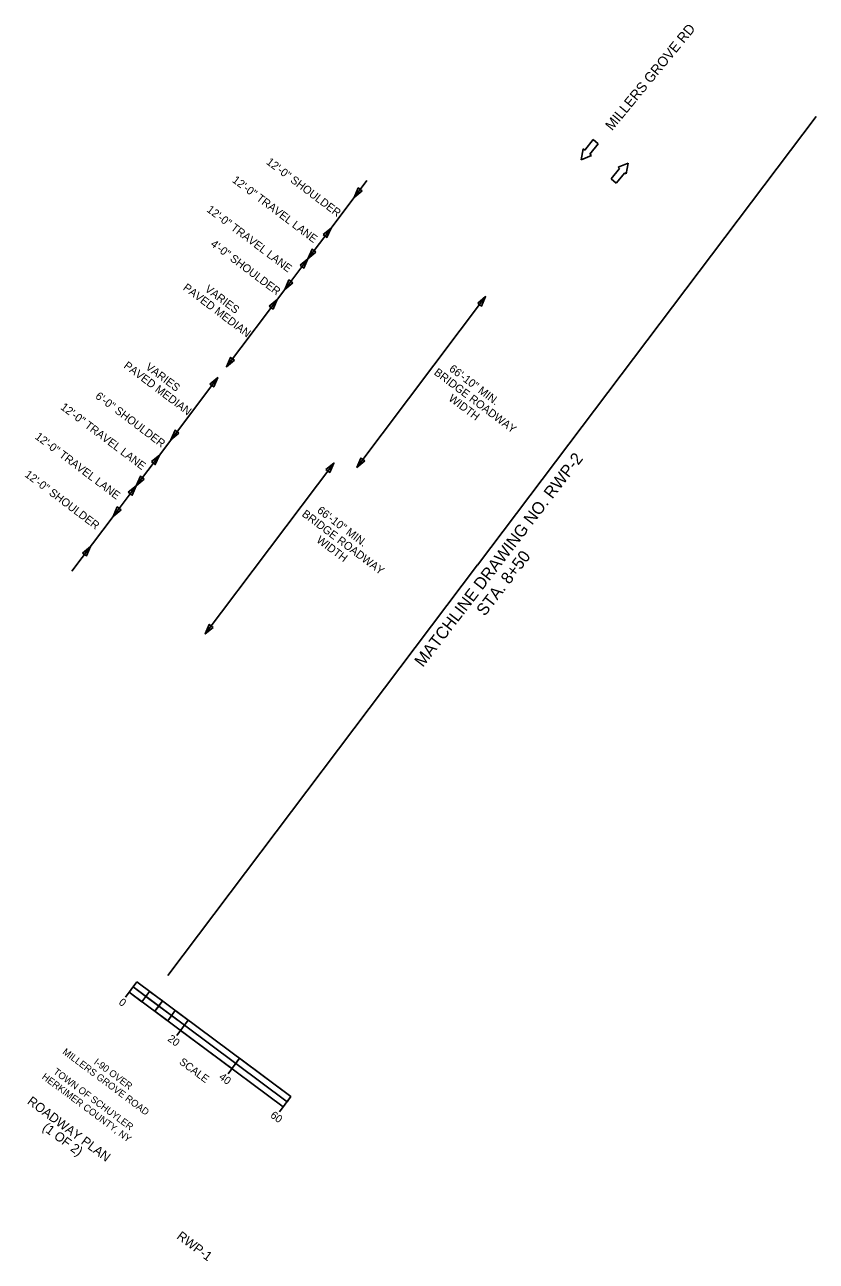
# Model space of a CAD drawing. Extents: x 337137 to 337603, y 1540940 to 1541587.
# Drawn here: x 337355.7 to 337603, y 1540940 to 1541326.3 of the extents above; entities that cross this region are included whole.
import ezdxf

# ---------------------------------------------------------------- set-up
doc = ezdxf.new("R2010")
doc.units = 0
for name, color, linetype in [('Default', 7, 'Continuous'), ('NML_P', 7, 'Continuous'), ('NSB_P', 7, 'Continuous'), ('NSB_P_T', 7, 'Continuous'), ('O_Details_Dimensions_Notes_P', 7, 'Continuous'), ('O_Details_Object Line 1_P', 7, 'Continuous')]:
    doc.layers.add(name, color=color, linetype=linetype)

msp = doc.modelspace()

# ---------------------------------------------------------------- linework, layer by layer
at = {"layer": 'NML_P'}
for p, q in [((337603.01, 1541297.57), (337497.22, 1541157.47)), ((337400.43, 1541029.19), (337497.15, 1541157.52)), ((337497.15, 1541157.52), (337497.22, 1541157.47))]:
    msp.add_line(p, q, dxfattribs=at)
at = {"layer": 'NSB_P'}
for p, q in [((337387.15, 1541022.45), (337390.73, 1541027.26)), ((337388.34, 1541024.05), (337436.46, 1540988.21)), ((337389.54, 1541025.65), (337437.66, 1540989.82)), ((337390.73, 1541027.26), (337438.85, 1540991.42)), ((337392.35, 1541021.06), (337393.55, 1541022.67)), ((337396.36, 1541018.08), (337398.75, 1541021.29)), ((337400.37, 1541015.09), (337402.76, 1541018.3)), ((337403.19, 1541010.5), (337406.77, 1541015.31)), ((337419.23, 1540998.56), (337422.81, 1541003.37)), ((337435.27, 1540986.61), (337438.85, 1540991.42))]:
    msp.add_line(p, q, dxfattribs=at)
for points in [[(337389.54, 1541025.65), (337393.55, 1541022.67), (337392.35, 1541021.06), (337388.34, 1541024.05)], [(337394.74, 1541024.27), (337398.75, 1541021.29), (337397.56, 1541019.68), (337393.55, 1541022.67)], [(337397.56, 1541019.68), (337401.57, 1541016.7), (337400.37, 1541015.09), (337396.36, 1541018.08)], [(337402.76, 1541018.3), (337406.77, 1541015.31), (337405.58, 1541013.71), (337401.57, 1541016.7)], [(337405.58, 1541013.71), (337421.62, 1541001.76), (337420.42, 1541000.16), (337404.38, 1541012.1)], [(337422.81, 1541003.37), (337438.85, 1540991.42), (337437.66, 1540989.82), (337421.62, 1541001.76)]]:
    msp.add_lwpolyline(points, close=True, dxfattribs=at)
at = {"layer": 'O_Details_Dimensions_Notes_P'}
for p, q in [((337451.42, 1541262.76), (337462.64, 1541277.65)), ((337444.2, 1541253.18), (337451.42, 1541262.76)), ((337436.98, 1541243.59), (337444.2, 1541253.18)), ((337418.75, 1541219.4), (337436.98, 1541243.59)), ((337459.49, 1541187.96), (337499.71, 1541241.33)), ((337397.78, 1541191.83), (337416.04, 1541216.05)), ((337390.56, 1541182.24), (337397.78, 1541191.83)), ((337412.09, 1541135.97), (337452.31, 1541189.34)), ((337383.34, 1541172.66), (337390.56, 1541182.24)), ((337370.45, 1541155.56), (337383.34, 1541172.66))]:
    msp.add_line(p, q, dxfattribs=at)
for points in [[(337461.12, 1541274.39), (337458.64, 1541272.34), (337459.93, 1541275.29)], [(337448.94, 1541260.72), (337451.42, 1541262.76), (337450.14, 1541259.81)], [(337446.68, 1541255.22), (337444.2, 1541253.18), (337445.48, 1541256.12)], [(337441.72, 1541251.13), (337444.2, 1541253.18), (337442.92, 1541250.23)], [(337439.46, 1541245.64), (337436.98, 1541243.59), (337438.26, 1541246.54)], [(337432.09, 1541238.36), (337434.57, 1541240.4), (337433.29, 1541237.45)], [(337497.23, 1541239.29), (337499.71, 1541241.33), (337498.43, 1541238.38)], [(337421.23, 1541221.45), (337418.75, 1541219.4), (337420.03, 1541222.35)], [(337413.56, 1541214.01), (337416.04, 1541216.05), (337414.76, 1541213.11)], [(337403.87, 1541198.66), (337401.39, 1541196.62), (337402.68, 1541199.57)], [(337395.3, 1541189.78), (337397.78, 1541191.83), (337396.5, 1541188.88)], [(337461.97, 1541190), (337459.49, 1541187.96), (337460.77, 1541190.91)], [(337449.83, 1541187.3), (337452.31, 1541189.34), (337451.03, 1541186.4)], [(337393.04, 1541184.29), (337390.56, 1541182.24), (337391.84, 1541185.19)], [(337388.08, 1541180.2), (337390.56, 1541182.24), (337389.28, 1541179.3)], [(337385.82, 1541174.71), (337383.34, 1541172.66), (337384.62, 1541175.61)], [(337373.78, 1541161.22), (337376.26, 1541163.27), (337374.98, 1541160.32)], [(337414.57, 1541138.01), (337412.09, 1541135.97), (337413.37, 1541138.92)]]:
    msp.add_lwpolyline(points, close=True, dxfattribs=at)
at = {"layer": 'O_Details_Object Line 1_P'}
for p, q in [((337530.19, 1541287.48), (337529.6, 1541284.11)), ((337530.66, 1541287.11), (337530.19, 1541287.48)), ((337530.66, 1541287.11), (337533.28, 1541290.39)), ((337532.3, 1541285.8), (337534.92, 1541289.08)), ((337534.92, 1541289.08), (337533.28, 1541290.39)), ((337532.77, 1541285.42), (337529.6, 1541284.11)), ((337532.77, 1541285.42), (337532.3, 1541285.8)), ((337541.08, 1541281.75), (337544.25, 1541283.04)), ((337543.64, 1541279.67), (337544.25, 1541283.04)), ((337541.54, 1541281.37), (337538.9, 1541278.1)), ((337543.17, 1541280.05), (337540.53, 1541276.78)), ((337541.54, 1541281.37), (337541.08, 1541281.75)), ((337543.64, 1541279.67), (337543.17, 1541280.05)), ((337540.53, 1541276.78), (337538.9, 1541278.1))]:
    msp.add_line(p, q, dxfattribs=at)

# ---------------------------------------------------------------- texts
at = {"layer": 'Default'}
for s, height, p in [('MILLERS GROVE ROAD', 2.16, (337367.32, 1541004.95)), ('I-90 OVER', 2.16, (337377.14, 1541001.8)), ('HERKIMER COUNTY, NY', 2.16, (337360.86, 1540997.19)), ('TOWN OF SCHUYLER', 2.16, (337364.45, 1540998.77)), ('ROADWAY PLAN', 2.88, (337356.26, 1540989.41)), ('(1 OF 2)', 2.88, (337361, 1540981.23)), ('RWP-1', 2.88, (337402.97, 1540947.26))]:
    msp.add_text(s, height=height, rotation=323.3259, dxfattribs=at).set_placement(p)
at = {"layer": 'NML_P'}
for s, height, p in [('MATCHLINE DRAWING NO. RWP-2', 3.7501, (337480.1, 1541125.34)), ('STA. 8+50', 3.75, (337499.44, 1541141.27))]:
    msp.add_text(s, height=height, rotation=52.4448, dxfattribs=at).set_placement(p)
at = {"layer": 'NSB_P_T'}
for s, p in [('0', (337384.87, 1541020.43)), ('20', (337400.15, 1541009.05)), ('SCALE', (337403.76, 1541001.81)), ('40', (337416.19, 1540997.11)), ('60', (337432.25, 1540985.15))]:
    msp.add_text(s, height=2.4, rotation=323.3259, dxfattribs=at).set_placement(p)
at = {"layer": 'O_Details_Dimensions_Notes_P'}
for s, height, rotation, p in [('MILLERS GROVE RD', 3.1251, 50.6167, (337539.21, 1541293)), ('12\'-0" SHOULDER', 2.5, 322.9962, (337430.96, 1541282.97)), ('12\'-0" TRAVEL LANE', 2.5, 322.9962, (337420.34, 1541277.3)), ('12\'-0" TRAVEL LANE', 2.5, 322.9962, (337412.36, 1541268.08)), ('4\'-0" SHOULDER', 2.5, 322.9962, (337413.56, 1541257.33)), ('PAVED MEDIAN', 2.5, 322.9962, (337404.96, 1541243.66)), ('VARIES', 2.5, 322.9962, (337411.78, 1541243.22)), ('PAVED MEDIAN', 2.5, 322.9962, (337386.43, 1541219.31)), ('VARIES', 2.5, 322.9962, (337393.25, 1541218.87)), ('BRIDGE ROADWAY ', 2.5, 322.9962, (337483.36, 1541217.19)), ('66\'-10" MIN.', 2.5, 322.9962, (337488.1, 1541218.32)), ('6\'-0" SHOULDER', 2.5, 322.9962, (337377.56, 1541209.79)), ('WIDTH', 2.5, 322.9962, (337487.92, 1541209.06)), ('12\'-0" TRAVEL LANE', 2.5, 322.9962, (337366.7, 1541206.36)), ('12\'-0" TRAVEL LANE', 2.5, 322.9962, (337358.72, 1541197.14)), ('12\'-0" SHOULDER', 2.5, 322.9962, (337355.51, 1541185.3)), ('BRIDGE ROADWAY ', 2.5, 322.9962, (337442.09, 1541172.96)), ('66\'-10" MIN.', 2.5, 322.9962, (337446.83, 1541174.09)), ('WIDTH', 2.5, 322.9962, (337446.64, 1541164.83))]:
    msp.add_text(s, height=height, rotation=rotation, dxfattribs=at).set_placement(p)

doc.saveas('drawing.dxf')
